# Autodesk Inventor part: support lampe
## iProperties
Created: 2011-01
Part Number: support lampe
Document SubType Name: Modeling
Designer: eric
Density: 1 g/cm^3
Mass: 3.00485 g
Surface Area: 55.9312 cm^2
Volume: 3.00485 cm^3
Author: eric
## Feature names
1. Base1
